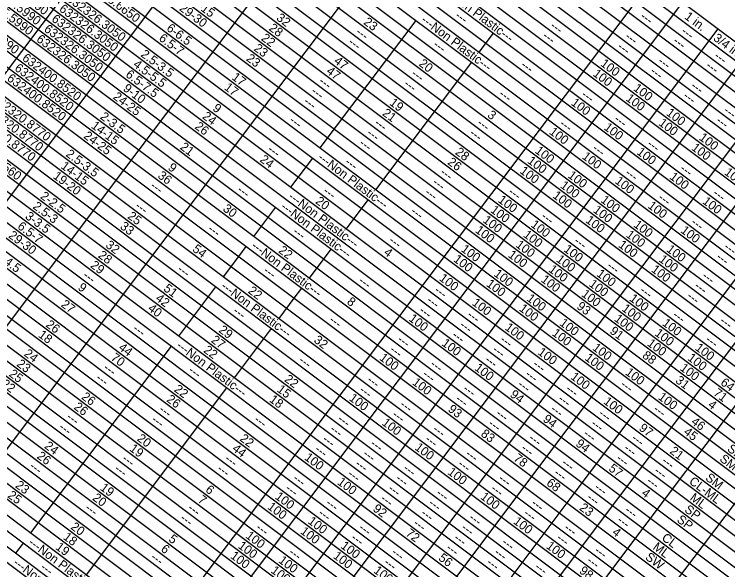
# Model space of a CAD drawing. Extents: x 627484.2 to 627514.4, y 367972.1 to 367996.9.
# Drawn here: x 627486.414 to 627490.816, y 367990.878 to 367994.309 of the extents above; entities that cross this region are included whole.
import ezdxf

# ---------------------------------------------------------------- set-up
doc = ezdxf.new("R2010")
doc.units = 0
doc.layers.add('Default', color=7, linetype='Continuous')

msp = doc.modelspace()

# ---------------------------------------------------------------- linework, layer by layer
at = {"layer": 'Default'}
for p, q in [((627487.3096, 367996.6915), (627492.549, 367992.7571)), ((627487.2628, 367996.6291), (627492.5022, 367992.6948)), ((627487.2159, 367996.5667), (627492.4553, 367992.6324)), ((627487.1691, 367996.5044), (627492.4085, 367992.57)), ((627487.1223, 367996.442), (627492.3617, 367992.5077)), ((627486.3352, 367993.9116), (627488.1823, 367996.3715)), ((627487.0754, 367996.3796), (627492.3148, 367992.4453)), ((627487.0344, 367996.325), (627492.2739, 367992.3907)), ((627486.9876, 367996.2627), (627492.227, 367992.3283)), ((627486.9408, 367996.2003), (627492.1802, 367992.266)), ((627486.8998, 367996.1457), (627492.1392, 367992.2114)), ((627486.719, 367993.6234), (627488.5661, 367996.0832)), ((627486.8529, 367996.0833), (627492.0924, 367992.149)), ((627486.8061, 367996.021), (627492.0455, 367992.0866)), ((627486.7651, 367995.9664), (627492.0045, 367992.0321)), ((627486.7183, 367995.904), (627491.9577, 367991.9697)), ((627486.6715, 367995.8416), (627491.9109, 367991.9073)), ((627486.6305, 367995.7871), (627491.8699, 367991.8527)), ((627487.0894, 367993.3453), (627488.9365, 367995.8052)), ((627486.5836, 367995.7247), (627491.8231, 367991.7904)), ((627486.5368, 367995.6623), (627491.7762, 367991.728)), ((627486.49, 367995.5999), (627491.7294, 367991.6656)), ((627486.449, 367995.5454), (627491.6884, 367991.611)), ((627487.4558, 367993.0702), (627489.3029, 367995.53)), ((627486.4021, 367995.483), (627491.6416, 367991.5487)), ((627486.3553, 367995.4206), (627491.5947, 367991.4863)), ((627486.3085, 367995.3583), (627491.5479, 367991.4239)), ((627486.2616, 367995.2959), (627491.5011, 367991.3616)), ((627486.2148, 367995.2335), (627491.4542, 367991.2992)), ((627486.1738, 367995.1789), (627491.4132, 367991.2446)), ((627486.127, 367995.1166), (627491.3664, 367991.1822)), ((627486.0801, 367995.0542), (627491.3196, 367991.1199)), ((627486.0392, 367994.9996), (627491.2786, 367991.0653)), ((627485.9923, 367994.9372), (627491.2317, 367991.0029)), ((627485.9455, 367994.8749), (627491.1849, 367990.9405)), ((627485.8987, 367994.8125), (627491.1381, 367990.8782)), ((627485.8518, 367994.7501), (627491.0912, 367990.8158)), ((627485.805, 367994.6877), (627491.0444, 367990.7534)), ((627487.187, 367990.3091), (627490.4568, 367994.6635)), ((627485.764, 367994.6332), (627491.0034, 367990.6988)), ((627485.7172, 367994.5708), (627490.9566, 367990.6365)), ((627485.6703, 367994.5084), (627490.9097, 367990.5741)), ((627490.3514, 367994.5232), (627491.9419, 367993.3289)), ((627485.6235, 367994.4461), (627490.8629, 367990.5117)), ((627485.5767, 367994.3837), (627490.8161, 367990.4494)), ((627488.7968, 367992.0632), (627490.5385, 367994.3827)), ((627485.5298, 367994.3213), (627490.7692, 367990.387)), ((627485.483, 367994.2589), (627490.7224, 367990.3246)), ((627488.3023, 367993.4831), (627488.8936, 367994.2705)), ((627489.0151, 367991.8993), (627490.7568, 367994.2187)), ((627485.4362, 367994.1966), (627490.6756, 367990.2622)), ((627489.2835, 367994.0753), (627489.3713, 367994.1922)), ((627485.3952, 367994.142), (627490.6346, 367990.2077)), ((627485.3483, 367994.0796), (627490.5877, 367990.1453)), ((627489.2022, 367991.7587), (627490.944, 367994.0782)), ((627485.3015, 367994.0172), (627490.5409, 367990.0829)), ((627488.6454, 367993.2255), (627489.2367, 367994.0129)), ((627485.2547, 367993.9549), (627490.4941, 367990.0205)), ((627485.2078, 367993.8925), (627490.4472, 367989.9582)), ((627489.4205, 367991.5948), (627491.1623, 367993.9143)), ((627485.161, 367993.8301), (627490.4004, 367989.8958)), ((627485.12, 367993.7755), (627490.3594, 367989.8412)), ((627489.6077, 367991.4543), (627491.3494, 367993.7738)), ((627485.0732, 367993.7132), (627490.3126, 367989.7788)), ((627485.0263, 367993.6508), (627490.2657, 367989.7165)), ((627484.9795, 367993.5884), (627490.2189, 367989.6541)), ((627485.2964, 367991.7288), (627486.719, 367993.6234)), ((627489.826, 367991.2904), (627491.5677, 367993.6099)), ((627484.9327, 367993.5261), (627490.1721, 367989.5917)), ((627484.8917, 367993.4715), (627490.1311, 367989.5372)), ((627490.0131, 367991.1499), (627491.7548, 367993.4694)), ((627490.2002, 367991.0094), (627492.0473, 367993.4692)), ((627484.8448, 367993.4091), (627490.0843, 367989.4748)), ((627488.1208, 367993.2414), (627488.2555, 367993.4207)), ((627484.798, 367993.3467), (627490.0374, 367989.4124)), ((627485.6667, 367991.4508), (627487.0894, 367993.3453)), ((627484.7512, 367993.2844), (627489.9906, 367989.35)), ((627490.4887, 367990.7927), (627492.3241, 367993.237)), ((627484.7043, 367993.222), (627489.9437, 367989.2877)), ((627484.6634, 367993.1674), (627489.9028, 367989.2331)), ((627488.4639, 367992.9838), (627488.5985, 367993.1631)), ((627484.6165, 367993.105), (627489.8559, 367989.1707)), ((627487.8925, 367992.9373), (627488.0272, 367993.1166)), ((627486.0331, 367991.1756), (627487.4558, 367993.0702)), ((627484.5697, 367993.0427), (627489.8091, 367989.1083)), ((627484.5228, 367992.9803), (627489.7623, 367989.046)), ((627484.4819, 367992.9257), (627489.7213, 367988.9914)), ((627484.435, 367992.8633), (627489.6744, 367988.929)), ((627487.7988, 367992.8126), (627487.8457, 367992.8749)), ((627488.2356, 367992.6797), (627488.3702, 367992.859)), ((627484.3882, 367992.801), (627489.6276, 367988.8666)), ((627487.7052, 367992.6878), (627487.7988, 367992.8126)), ((627484.3414, 367992.7386), (627489.5808, 367988.8043)), ((627484.2945, 367992.6762), (627489.5339, 367988.7419)), ((627484.2477, 367992.6139), (627489.4871, 367988.6795)), ((627487.43, 367992.3214), (627487.6583, 367992.6254)), ((627488.1419, 367992.555), (627488.1887, 367992.6173)), ((627484.2008, 367992.5515), (627489.4403, 367988.6172)), ((627488.0482, 367992.4302), (627488.1419, 367992.555)), ((627487.7731, 367992.0638), (627488.0014, 367992.3678)), ((627486.5167, 367991.1051), (627487.3832, 367992.259)), ((627487.3742, 367990.1686), (627488.7968, 367992.0632)), ((627486.8598, 367990.8475), (627487.7262, 367992.0014)), ((627487.5925, 367990.0047), (627489.0151, 367991.8993)), ((627487.7796, 367989.8642), (627489.2022, 367991.7587)), ((627487.9979, 367989.7002), (627489.4205, 367991.5948)), ((627488.185, 367989.5597), (627489.6077, 367991.4543)), ((627488.4033, 367989.3958), (627489.826, 367991.2904)), ((627488.5904, 367989.2553), (627490.0131, 367991.1499)), ((627486.423, 367990.9804), (627486.4699, 367991.0427)), ((627488.7775, 367989.1148), (627490.2002, 367991.0094))]:
    msp.add_line(p, q, dxfattribs=at)

# ---------------------------------------------------------------- texts
for s, p in [('381645.5990', (627486.2559, 367994.5586)), ('381645.5990', (627486.2091, 367994.4962)), ('632323.6650', (627486.8212, 367994.5121)), ('381645.5990', (627486.1622, 367994.4339)), ('---Non Plastic---', (627489.0548, 367994.4443)), ('632326.3050', (627486.7334, 367994.3951)), ('14-15', (627487.4756, 367994.3987)), ('29-30', (627487.4278, 367994.3371)), ('381744.7990', (627486.0744, 367994.3169)), ('632326.3050', (627486.6866, 367994.3328)), ('632326.3050', (627486.6397, 367994.2704)), ('32', (627488.027, 367994.2773)), ('23', (627488.5646, 367994.2516)), ('---', (627489.1287, 367994.2913)), ('---', (627490.2714, 367994.2867)), ('1 in.', (627490.5451, 367994.2854)), ('632326.3050', (627486.5929, 367994.208)), ('6-6.5', (627487.349, 367994.2133)), ('28', (627487.9807, 367994.2145)), ('---Non Plastic---', (627488.9201, 367994.265)), ('---', (627489.7156, 367994.2285)), ('---', (627488.5164, 367994.1902)), ('---', (627490.5245, 367994.1942)), ('632326.3050', (627486.5461, 367994.1456)), ('6.5-7', (627487.3015, 367994.1514)), ('22', (627487.9333, 367994.1525)), ('---', (627489.6688, 367994.1662)), ('---', (627490.1777, 367994.162)), ('3/4 in.', (627490.7225, 367994.1522)), ('23', (627487.8878, 367994.0891)), ('---', (627488.4695, 367994.1279)), ('---', (627488.9941, 367994.112)), ('---', (627490.1309, 367994.0996)), ('---', (627490.4741, 367994.1345)), ('632400.8520', (627486.4583, 367994.0287)), ('2.5-3.5', (627487.19, 367994.0523)), ('23', (627487.841, 367994.0268)), ('47', (627488.3818, 367994.0108)), ('20', (627488.9061, 367993.9951)), ('100', (627490.0267, 367993.995)), ('---', (627490.3805, 367994.0098)), ('---', (627490.7272, 367994.042)), ('632400.8520', (627486.4114, 367993.9663)), ('4.5-5.5', (627487.1432, 367993.9899)), ('47', (627488.335, 367993.9484)), ('---', (627489.5341, 367993.9868)), ('---', (627490.6768, 367993.9823)), ('632400.8520', (627486.3646, 367993.9039)), ('6.5-7.5', (627487.0964, 367993.9275)), ('17', (627487.7519, 367993.9108)), ('---', (627488.8594, 367993.9326)), ('100', (627489.9798, 367993.9326)), ('---', (627490.3336, 367993.9474)), ('---', (627488.288, 367993.8862)), ('9-10', (627487.081, 367993.8415)), ('17', (627487.7051, 367993.8484)), ('---', (627488.8126, 367993.8703)), ('100', (627490.2294, 367993.8427)), ('---', (627490.5832, 367993.8575)), ('632320.8770', (627486.2709, 367993.7792)), ('24-25', (627487.0189, 367993.7906)), ('---', (627488.2412, 367993.8238)), ('---', (627489.3995, 367993.8075)), ('---', (627489.9084, 367993.8033)), ('100', (627490.1826, 367993.7804)), ('---', (627490.5363, 367993.7952)), ('---', (627488.1944, 367993.7614)), ('19', (627488.7248, 367993.7533)), ('100', (627489.8452, 367993.7533)), ('632320.8770', (627486.2241, 367993.7168)), ('9', (627487.6335, 367993.7193)), ('21', (627488.6806, 367993.6889)), ('3', (627489.3293, 367993.6773)), ('100', (627490.4321, 367993.6905)), ('---', (627490.7859, 367993.7053)), ('632320.8770', (627486.1772, 367993.6545)), ('2-3.5', (627486.9392, 367993.6675)), ('24', (627487.5701, 367993.6693)), ('14-15', (627486.8843, 367993.6113)), ('26', (627487.5234, 367993.6068)), ('---', (627488.1065, 367993.6445)), ('---', (627488.6311, 367993.6286)), ('---', (627489.2648, 367993.6282)), ('---', (627489.7738, 367993.624)), ('100', (627490.0479, 367993.6011)), ('---', (627490.1111, 367993.6511)), ('100', (627490.3853, 367993.6282)), ('---', (627490.739, 367993.6429)), ('24-25', (627486.8374, 367993.5489)), ('---', (627488.5842, 367993.5662)), ('---', (627489.218, 367993.5658)), ('100', (627489.7105, 367993.574)), ('632403.1560', (627486.0894, 367993.5375)), ('100', (627490.6348, 367993.5383)), ('21', (627487.4325, 367993.48)), ('---', (627488.5374, 367993.5038)), ('---', (627490.3139, 367993.4989)), ('100', (627490.588, 367993.4759)), ('2.5-3.5', (627486.7275, 367993.4363)), ('---', (627487.9719, 367993.4652)), ('28', (627489.1307, 367993.4485)), ('100', (627489.6227, 367993.457)), ('100', (627489.9132, 367993.4217)), ('---', (627489.9765, 367993.4718)), ('100', (627490.2506, 367993.4488)), ('24', (627487.9249, 367993.4029)), ('---Non Plastic---', (627488.282, 367993.4152)), ('26', (627489.0833, 367993.3866)), ('100', (627489.5759, 367993.3946)), ('14-15', (627486.6969, 367993.3618)), ('9', (627487.3583, 367993.3528)), ('---', (627488.4496, 367993.3869)), ('100', (627489.529, 367993.3323)), ('---', (627490.5166, 367993.3467)), ('19-20', (627486.6491, 367993.3001)), ('36', (627487.2951, 367993.3028)), ('---', (627489.0365, 367993.3241)), ('100', (627489.8254, 367993.3048)), ('---', (627490.1792, 367993.3196)), ('100', (627490.4533, 367993.2966)), ('100', (627490.7907, 367993.3237)), ('---', (627488.9897, 367993.2618)), ('100', (627489.7786, 367993.2424)), ('100', (627490.116, 367993.2695)), ('---', (627487.2483, 367993.2403)), ('---', (627487.7845, 367993.2157)), ('2-2.5', (627486.5704, 367993.1763)), ('---Non Plastic---', (627488.1005, 367993.1735)), ('---', (627488.3149, 367993.2076)), ('---', (627488.9428, 367993.1994)), ('100', (627489.3944, 367993.1529)), ('---', (627489.4576, 367993.203)), ('100', (627489.7318, 367993.18)), ('100', (627490.0281, 367993.1526)), ('---', (627490.3819, 367993.1674)), ('---', (627490.7193, 367993.1945)), ('2.5-3', (627486.5241, 367993.1135)), ('20', (627488.2679, 367993.1453)), ('100', (627490.3187, 367993.1173)), ('100', (627490.656, 367993.1444)), ('---', (627487.1546, 367993.1156)), ('30', (627487.6966, 367993.0988)), ('---Non Plastic---', (627488.0537, 367993.1111)), ('---', (627488.855, 367993.0824)), ('100', (627489.3476, 367993.0906)), ('100', (627489.9813, 367993.0902)), ('3-3.5', (627486.4767, 367993.0516)), ('25', (627487.1086, 367993.0526)), ('100', (627489.3007, 367993.0282)), ('---', (627489.6603, 367993.0508)), ('100', (627489.9345, 367993.0278)), ('6.5-7', (627486.4292, 367992.9897)), ('33', (627487.0623, 367992.9898)), ('100', (627489.5971, 367993.0007)), ('100', (627490.2309, 367993.0003)), ('---', (627490.5846, 367993.0151)), ('29-30', (627486.3739, 367992.9337)), ('---', (627487.603, 367992.974)), ('---', (627488.1276, 367992.9581)), ('100', (627489.2539, 367992.9658)), ('100', (627489.5503, 367992.9383)), ('100', (627490.184, 367992.938)), ('100', (627490.5214, 367992.9651)), ('32', (627486.9732, 367992.8739)), ('54', (627487.5092, 367992.8494)), ('---Non Plastic---', (627487.8722, 367992.8694)), ('22', (627488.0398, 367992.8411)), ('---', (627488.7204, 367992.9031)), ('100', (627489.1661, 367992.8489)), ('100', (627489.5034, 367992.876)), ('100', (627489.7998, 367992.8485)), ('---', (627489.8631, 367992.8986)), ('100', (627490.1372, 367992.8756)), ('100', (627490.4336, 367992.8481)), ('---', (627490.7873, 367992.8629)), ('4-4.5', (627486.2952, 367992.8099)), ('28', (627486.9268, 367992.8111)), ('4', (627488.6896, 367992.8287)), ('100', (627489.4566, 367992.8136)), ('100', (627489.1192, 367992.7865)), ('100', (627489.753, 367992.7861)), ('100', (627490.3867, 367992.7858)), ('---', (627490.7405, 367992.8005)), ('29', (627486.8795, 367992.7491)), ('100', (627489.7061, 367992.7238)), ('---', (627490.0658, 367992.7463)), ('100', (627490.3399, 367992.7234)), ('---', (627486.8326, 367992.6868)), ('---', (627487.4157, 367992.7245)), ('---', (627487.9461, 367992.7164)), ('100', (627489.0314, 367992.6695)), ('100', (627489.3688, 367992.6966)), ('100', (627490.0025, 367992.6963)), ('---', (627490.6527, 367992.6836)), ('---', (627488.533, 367992.6536)), ('100', (627489.3219, 367992.6343)), ('100', (627489.6593, 367992.6614)), ('100', (627489.9557, 367992.6339)), ('9', (627486.8021, 367992.6122)), ('51', (627487.3306, 367992.6055)), ('---Non Plastic---', (627487.6848, 367992.6199)), ('22', (627487.8525, 367992.5916)), ('---', (627490.6058, 367992.6212)), ('42', (627487.2811, 367992.5451)), ('---', (627489.001, 367992.5949)), ('100', (627489.5715, 367992.5444)), ('100', (627489.9089, 367992.5715)), ('100', (627490.2052, 367992.5441)), ('---', (627490.2685, 367992.5941)), ('---', (627490.559, 367992.5588)), ('27', (627486.6981, 367992.5074)), ('8', (627488.462, 367992.5241)), ('---', (627488.9541, 367992.5325)), ('100', (627489.2341, 367992.5173)), ('93', (627489.8798, 367992.4958)), ('40', (627487.2341, 367992.4829)), ('---', (627487.7588, 367992.4669)), ('---', (627488.9073, 367992.4701)), ('100', (627489.5247, 367992.4821)), ('100', (627490.1584, 367992.4817)), ('100', (627488.8441, 367992.4201)), ('---', (627489.2037, 367992.4426)), ('100', (627490.1116, 367992.4193)), ('---', (627490.4712, 367992.4419)), ('26', (627486.6042, 367992.3828)), ('---', (627488.3515, 367992.4119)), ('---', (627489.1569, 367992.3803)), ('100', (627489.4368, 367992.3651)), ('100', (627489.7742, 367992.3922)), ('100', (627490.4079, 367992.3918)), ('---', (627490.7617, 367992.4066)), ('18', (627486.558, 367992.3199)), ('---', (627487.1405, 367992.358)), ('29', (627487.671, 367992.3499)), ('100', (627489.7274, 367992.3298)), ('91', (627490.0838, 367992.3426)), ('100', (627490.3611, 367992.3295)), ('27', (627487.6242, 367992.2874)), ('32', (627488.2579, 367992.2872)), ('---', (627488.7727, 367992.2908)), ('---', (627489.11, 367992.3179)), ('---', (627489.4064, 367992.2904)), ('---', (627490.6739, 367992.2897)), ('44', (627487.0525, 367992.2412)), ('---Non Plastic---', (627487.4097, 367992.2535)), ('22', (627487.5773, 367992.2252)), ('100', (627489.0468, 367992.2678)), ('100', (627489.9769, 367992.24)), ('100', (627490.3143, 367992.2671)), ('100', (627490.6107, 367992.2396)), ('24', (627486.4695, 367992.2035)), ('70', (627487.0057, 367992.1788)), ('---', (627488.7258, 367992.2284)), ('---', (627489.3596, 367992.228)), ('100', (627489.6395, 367992.2129)), ('88', (627490.2844, 367992.192)), ('23', (627486.4242, 367992.14)), ('---', (627488.1642, 367992.1624)), ('100', (627488.6626, 367992.1784)), ('---', (627489.3127, 367992.1657)), ('100', (627489.9301, 367992.1776)), ('100', (627490.5638, 367992.1773)), ('---', (627486.9591, 367992.1163)), ('---', (627488.9754, 367992.1386)), ('100', (627489.2495, 367992.1156)), ('---', (627489.6091, 367992.1382)), ('100', (627490.517, 367992.1149)), ('25', (627486.3768, 367992.078)), ('---', (627487.4836, 367992.1004)), ('---', (627488.9285, 367992.0762)), ('---', (627489.5623, 367992.0758)), ('100', (627489.8423, 367992.0607)), ('100', (627490.1796, 367992.0878)), ('22', (627486.3292, 367992.0163)), ('---', (627486.9122, 367992.054)), ('22', (627488.0764, 367992.0455)), ('---', (627488.5853, 367992.0413)), ('100', (627488.8653, 367992.0261)), ('31', (627490.4892, 367992.0382)), ('64', (627490.7672, 367992.0246)), ('22', (627487.3958, 367991.9835)), ('15', (627488.0303, 367991.9825)), ('---', (627488.5385, 367991.9789)), ('---', (627489.1781, 367991.9864)), ('---', (627489.5154, 367992.0135)), ('---', (627489.8118, 367991.986)), ('---', (627490.1492, 367992.0131)), ('71', (627490.7232, 367991.96)), ('26', (627486.8243, 367991.9371)), ('26', (627487.3489, 367991.9212)), ('18', (627487.9832, 367991.9203)), ('100', (627488.4752, 367991.9289)), ('94', (627489.4684, 367991.9512)), ('100', (627490.3823, 367991.9356)), ('26', (627486.7775, 367991.8747)), ('---', (627489.1312, 367991.924)), ('---', (627489.765, 367991.9236)), ('100', (627490.045, 367991.9085)), ('4', (627490.6897, 367991.8876)), ('---', (627487.3021, 367991.8587)), ('---', (627488.788, 367991.8891)), ('93', (627489.0858, 367991.8606)), ('---', (627489.7182, 367991.8612)), ('---', (627490.3519, 367991.8609)), ('---', (627486.7307, 367991.8123)), ('---', (627488.7412, 367991.8267)), ('---', (627489.3808, 367991.8341)), ('94', (627489.6711, 367991.799)), ('---', (627490.0145, 367991.8338)), ('---', (627487.2553, 367991.7964)), ('---', (627487.889, 367991.796)), ('---', (627488.4038, 367991.7996)), ('100', (627488.6779, 367991.7767)), ('---', (627489.334, 367991.7718)), ('---', (627489.9677, 367991.7714)), ('97', (627490.2642, 367991.7438)), ('46', (627490.5858, 367991.7828)), ('---', (627486.6839, 367991.7499)), ('---', (627488.357, 367991.7372)), ('---', (627488.9907, 367991.7369)), ('83', (627489.2885, 367991.7083)), ('45', (627490.5398, 367991.7197)), ('20', (627487.1673, 367991.6795)), ('22', (627487.8012, 367991.679)), ('---', (627488.3101, 367991.6749)), ('---', (627488.9439, 367991.6745)), ('---', (627489.5835, 367991.6819)), ('---', (627489.9209, 367991.709)), ('---', (627490.2172, 367991.6815)), ('24', (627486.5959, 367991.6331)), ('19', (627487.1207, 367991.617)), ('44', (627487.7542, 367991.6168)), ('---', (627488.6065, 367991.6474)), ('100', (627488.8807, 367991.6244)), ('94', (627489.8738, 367991.6468)), ('SM', (627490.8086, 367991.6155)), ('26', (627486.5492, 367991.5706)), ('---', (627488.2633, 367991.6125)), ('---', (627488.5597, 367991.585)), ('---', (627489.1934, 367991.5846)), ('---', (627489.5367, 367991.6195)), ('---', (627490.1704, 367991.6192)), ('21', (627490.4539, 367991.6014)), ('---', (627487.0738, 367991.5547)), ('---', (627487.7075, 367991.5543)), ('100', (627488.2001, 367991.5624)), ('78', (627489.4904, 367991.5568)), ('---', (627490.1236, 367991.5568)), ('---', (627490.4044, 367991.541)), ('SM', (627490.7617, 367991.5531)), ('---', (627486.5024, 367991.5082)), ('---', (627488.5129, 367991.5226)), ('---', (627488.8092, 367991.4952)), ('---', (627489.1466, 367991.5223)), ('---', (627489.7862, 367991.5297)), ('57', (627490.0769, 367991.4943)), ('---', (627487.0269, 367991.4923)), ('---', (627487.6607, 367991.4919)), ('---', (627488.466, 367991.4603)), ('100', (627489.0834, 367991.4722)), ('---', (627489.7394, 367991.4673)), ('---', (627490.3575, 367991.4787)), ('SM', (627490.6739, 367991.4362)), ('23', (627486.416, 367991.3902)), ('---', (627488.1287, 367991.4332)), ('100', (627488.4028, 367991.4102)), ('---', (627488.7624, 367991.4328)), ('---', (627489.3962, 367991.4324)), ('68', (627489.6931, 367991.4045)), ('---', (627490.3107, 367991.4163)), ('CL-ML', (627490.573, 367991.4144)), ('19', (627486.9392, 367991.3753)), ('6', (627487.589, 367991.3628)), ('---', (627488.0818, 367991.3708)), ('---', (627488.7156, 367991.3704)), ('---', (627489.3493, 367991.3701)), ('---', (627489.9889, 367991.3775)), ('25', (627486.3686, 367991.3283)), ('20', (627486.8921, 367991.3131)), ('7', (627487.5424, 367991.3003)), ('100', (627488.0186, 367991.3207)), ('---', (627489.012, 367991.3429)), ('100', (627489.2861, 367991.32)), ('4', (627490.2799, 367991.3419)), ('ML', (627490.5785, 367991.3128)), ('---', (627488.3314, 367991.2809)), ('---', (627488.6687, 367991.308)), ('---', (627488.9651, 367991.2806)), ('---', (627489.5989, 367991.2802)), ('---', (627489.9421, 367991.3151)), ('---', (627486.8454, 367991.2506)), ('---', (627487.4792, 367991.2502)), ('100', (627487.9717, 367991.2584)), ('92', (627488.6219, 367991.2456)), ('23', (627489.8966, 367991.2517)), ('---', (627490.176, 367991.237)), ('SP', (627490.5447, 367991.2406)), ('---', (627487.4324, 367991.1879)), ('---', (627488.2845, 367991.2186)), ('---', (627488.9183, 367991.2182)), ('---', (627489.2147, 367991.1907)), ('---', (627489.552, 367991.2178)), ('SP', (627490.4979, 367991.1782)), ('20', (627486.7575, 367991.1338)), ('100', (627488.2213, 367991.1685)), ('---', (627488.8714, 367991.1558)), ('100', (627489.4888, 367991.1678)), ('---', (627490.1292, 367991.1746)), ('---', (627487.9003, 367991.1291)), ('100', (627488.1745, 367991.1061)), ('---', (627488.5341, 367991.1287)), ('72', (627488.8246, 367991.0934)), ('---', (627489.1678, 367991.1284)), ('---', (627489.8016, 367991.128)), ('4', (627490.0984, 367991.1002)), ('18', (627486.7113, 367991.0709)), ('5', (627487.3616, 367991.0581)), ('100', (627487.8371, 367991.079)), ('---', (627488.4872, 367991.0664)), ('---', (627489.121, 367991.066)), ('---', (627489.7547, 367991.0656)), ('CL', (627490.4042, 367991.0656)), ('---Non Plastic---', (627486.4964, 367991.0372)), ('19', (627486.664, 367991.0089)), ('6', (627487.3139, 367990.9964)), ('100', (627487.7902, 367991.0167)), ('100', (627488.424, 367991.0163)), ('---', (627489.4174, 367991.0385)), ('100', (627489.6915, 367991.0156)), ('ML', (627490.3502, 367991.0087)), ('100', (627487.7434, 367990.9543)), ('---', (627488.103, 367990.9769)), ('100', (627488.3772, 367990.9539)), ('---', (627488.7368, 367990.9765)), ('---', (627489.0742, 367991.0036)), ('---', (627489.3705, 367990.9761)), ('---', (627489.9887, 367990.9875)), ('---', (627487.2509, 367990.9462)), ('100', (627488.0398, 367990.9268)), ('56', (627489.0272, 367990.9413)), ('---', (627489.9419, 367990.9251)), ('SW', (627490.3029, 367990.9466)), ('---Non Plastic---', (627486.4027, 367990.9125)), ('---', (627486.5703, 367990.8842)), ('100', (627487.993, 367990.8644)), ('100', (627488.6267, 367990.8641)), ('---', (627488.69, 367990.9141)), ('---', (627489.3237, 367990.9138)), ('---', (627489.6201, 367990.8863)), ('98', (627489.8956, 367990.8623))]:
    msp.add_text(s, height=0.055, rotation=323.0968, dxfattribs=at).set_placement(p)

doc.saveas('drawing.dxf')
